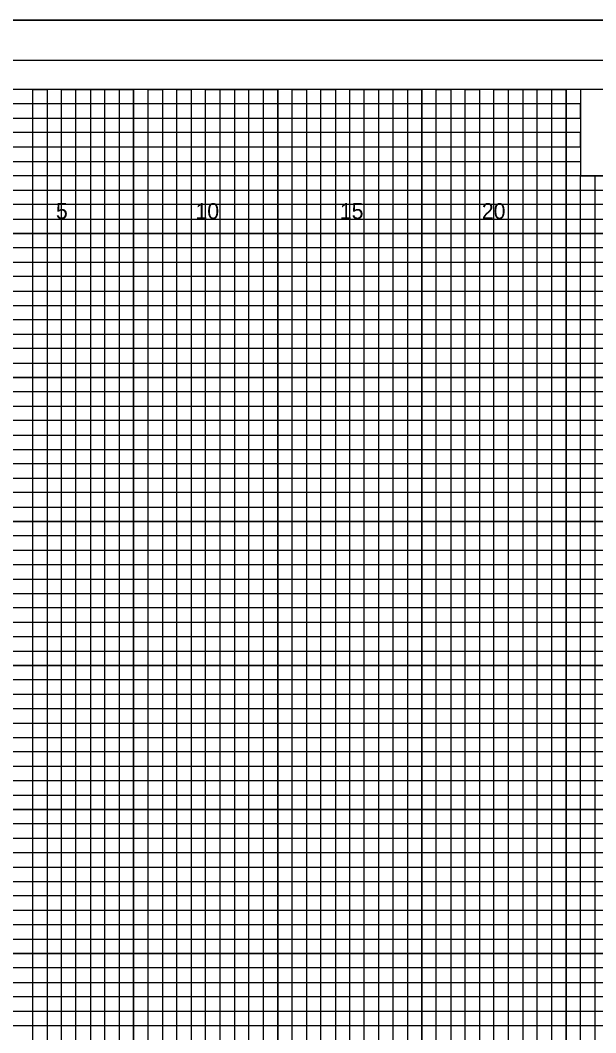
# Model space of a CAD drawing. Extents: x -4 to 103, y -2 to 67.
# Drawn here: x 54.82 to 74.78, y 32.25 to 67.4 of the extents above; entities that cross this region are included whole.
import ezdxf

# ---------------------------------------------------------------- set-up
doc = ezdxf.new("R2010")
doc.units = 0
for name, color, linetype in [('Exist XS Ground Line', 7, 'Continuous'), ('Old_Level_10', 7, 'Continuous'), ('Old_Level_16', 7, 'Continuous'), ('Old_Level_3', 7, 'Continuous'), ('Old_Level_5', 7, 'Continuous'), ('Old_Level_8', 7, 'Continuous'), ('Prop XS Dump Level', 7, 'Continuous'), ('Prop XS Finish Grade', 7, 'Continuous')]:
    doc.layers.add(name, color=color, linetype=linetype)

msp = doc.modelspace()

# ---------------------------------------------------------------- linework, layer by layer
at = {"layer": 'Exist XS Ground Line'}
msp.add_lwpolyline([(103, 66), (-2.8, 66), (-2.8, -1), (103, -1)], close=True, dxfattribs=at)
at = {"layer": 'Old_Level_10'}
for p, q in [((56.25, 0), (56.25, 65)), ((58.75, 0), (58.75, 65)), ((61.25, 0), (61.25, 65)), ((63.75, 0), (63.75, 65)), ((66.25, 0), (66.25, 65)), ((68.75, 0), (68.75, 65)), ((71.25, 0), (71.25, 65)), ((73.75, 0), (73.75, 65)), ((0, 62.5), (74.25, 62.5)), ((0, 60), (102.5, 60)), ((0, 57.5), (102.5, 57.5)), ((0, 55), (102.5, 55)), ((0, 52.5), (102.5, 52.5)), ((0, 50), (102.5, 50)), ((0, 47.5), (102.5, 47.5)), ((0, 45), (102.5, 45)), ((0, 42.5), (102.5, 42.5)), ((0, 40), (102.5, 40)), ((0, 37.5), (102.5, 37.5)), ((0, 35), (102.5, 35)), ((0, 32.5), (102.5, 32.5))]:
    msp.add_line(p, q, dxfattribs=at)
at = {"layer": 'Old_Level_3'}
msp.add_line((-3.5, 67.4), (103.4, 67.4), dxfattribs=at)
at = {"layer": 'Old_Level_5'}
msp.add_lwpolyline([(103.4, 67.4), (-3.5, 67.4), (-3.5, -2.425), (103.4, -2.425)], close=True, dxfattribs=at)
at = {"layer": 'Old_Level_8'}
for points in [[(56.25, 0), (56.25, 65), (58.75, 65), (58.75, 0)], [(61.25, 0), (61.25, 65), (63.75, 65), (63.75, 0)], [(66.25, 0), (66.25, 65), (68.75, 65), (68.75, 0)], [(71.25, 0), (71.25, 65), (73.75, 65), (73.75, 0)], [(0, 62.5), (74.25, 62.5)], [(0, 57.5), (102.5, 57.5), (102.5, 60), (0, 60)], [(0, 52.5), (102.5, 52.5), (102.5, 55), (0, 55)], [(0, 47.5), (102.5, 47.5), (102.5, 50), (0, 50)], [(0, 42.5), (102.5, 42.5), (102.5, 45), (0, 45)], [(0, 37.5), (102.5, 37.5), (102.5, 40), (0, 40)], [(0, 32.5), (102.5, 32.5), (102.5, 35), (0, 35)]]:
    msp.add_lwpolyline(points, dxfattribs=at)
at = {"layer": 'Prop XS Dump Level'}
for points in [[(102.5, 65), (0, 65), (0, 0), (102.5, 0)], [(83.75, 65), (74.25, 65), (74.25, 62), (83.75, 62)]]:
    msp.add_lwpolyline(points, close=True, dxfattribs=at)
at = {"layer": 'Prop XS Finish Grade'}
for points in [[(55.25, 0), (55.25, 65), (55.75, 65), (55.75, 0)], [(56.75, 0), (56.75, 65), (57.25, 65), (57.25, 0)], [(57.75, 0), (57.75, 65), (58.25, 65), (58.25, 0)], [(59.25, 0), (59.25, 65), (59.75, 65), (59.75, 0)], [(60.25, 0), (60.25, 65), (60.75, 65), (60.75, 0)], [(61.75, 0), (61.75, 65), (62.25, 65), (62.25, 0)], [(62.75, 0), (62.75, 65), (63.25, 65), (63.25, 0)], [(64.25, 0), (64.25, 65), (64.75, 65), (64.75, 0)], [(65.25, 0), (65.25, 65), (65.75, 65), (65.75, 0)], [(66.75, 0), (66.75, 65), (67.25, 65), (67.25, 0)], [(67.75, 0), (67.75, 65), (68.25, 65), (68.25, 0)], [(69.25, 0), (69.25, 65)], [(69.25, 65), (69.75, 65), (69.75, 0)], [(70.25, 0), (70.25, 65), (70.75, 65), (70.75, 0)], [(71.75, 0), (71.75, 65), (72.25, 65), (72.25, 0)], [(72.75, 0), (72.75, 65), (73.25, 65), (73.25, 0)], [(0, 62), (0, 63), (74.25, 63), (74.25, 63.5), (0, 63.5), (0, 64), (74.25, 64), (74.25, 64.5), (0, 64.5)], [(0, 61.5), (102.5, 61.5), (102.5, 62), (0, 62)], [(74.25, 0), (74.25, 62), (74.75, 62), (74.75, 0)], [(0, 60.5), (102.5, 60.5), (102.5, 61), (0, 61)], [(0, 59), (102.5, 59), (102.5, 59.5), (0, 59.5)], [(0, 58), (102.5, 58), (102.5, 58.5), (0, 58.5)], [(0, 56.5), (102.5, 56.5), (102.5, 57), (0, 57)], [(0, 55.5), (102.5, 55.5), (102.5, 56), (0, 56)], [(0, 54), (102.5, 54), (102.5, 54.5), (0, 54.5)], [(0, 53), (102.5, 53), (102.5, 53.5), (0, 53.5)], [(0, 51.5), (102.5, 51.5), (102.5, 52), (0, 52)], [(0, 50.5), (102.5, 50.5), (102.5, 51), (0, 51)], [(0, 49), (102.5, 49), (102.5, 49.5), (0, 49.5)], [(0, 48), (102.5, 48), (102.5, 48.5), (0, 48.5)], [(0, 46.5), (102.5, 46.5), (102.5, 47), (0, 47)], [(0, 45.5), (102.5, 45.5), (102.5, 46), (0, 46)], [(0, 44), (102.5, 44), (102.5, 44.5), (0, 44.5)], [(0, 43), (102.5, 43), (102.5, 43.5), (0, 43.5)], [(0, 41.5), (102.5, 41.5), (102.5, 42), (0, 42)], [(0, 40.5), (102.5, 40.5), (102.5, 41), (0, 41)], [(0, 39), (102.5, 39), (102.5, 39.5), (0, 39.5)], [(0, 38), (102.5, 38), (102.5, 38.5), (0, 38.5)], [(0, 36.5), (102.5, 36.5), (102.5, 37), (0, 37)], [(0, 35.5), (102.5, 35.5), (102.5, 36), (0, 36)], [(0, 34), (102.5, 34), (102.5, 34.5), (0, 34.5)], [(0, 33), (102.5, 33), (102.5, 33.5), (0, 33.5)]]:
    msp.add_lwpolyline(points, dxfattribs=at)

# ---------------------------------------------------------------- texts
at = {"layer": 'Old_Level_16'}
for s, p in [('5', (56.0574, 60.5)), ('10', (60.8971, 60.5)), ('15', (65.9057, 60.5)), ('20', (70.8312, 60.5))]:
    msp.add_text(s, height=0.55, dxfattribs=at).set_placement(p)

doc.saveas('drawing.dxf')
